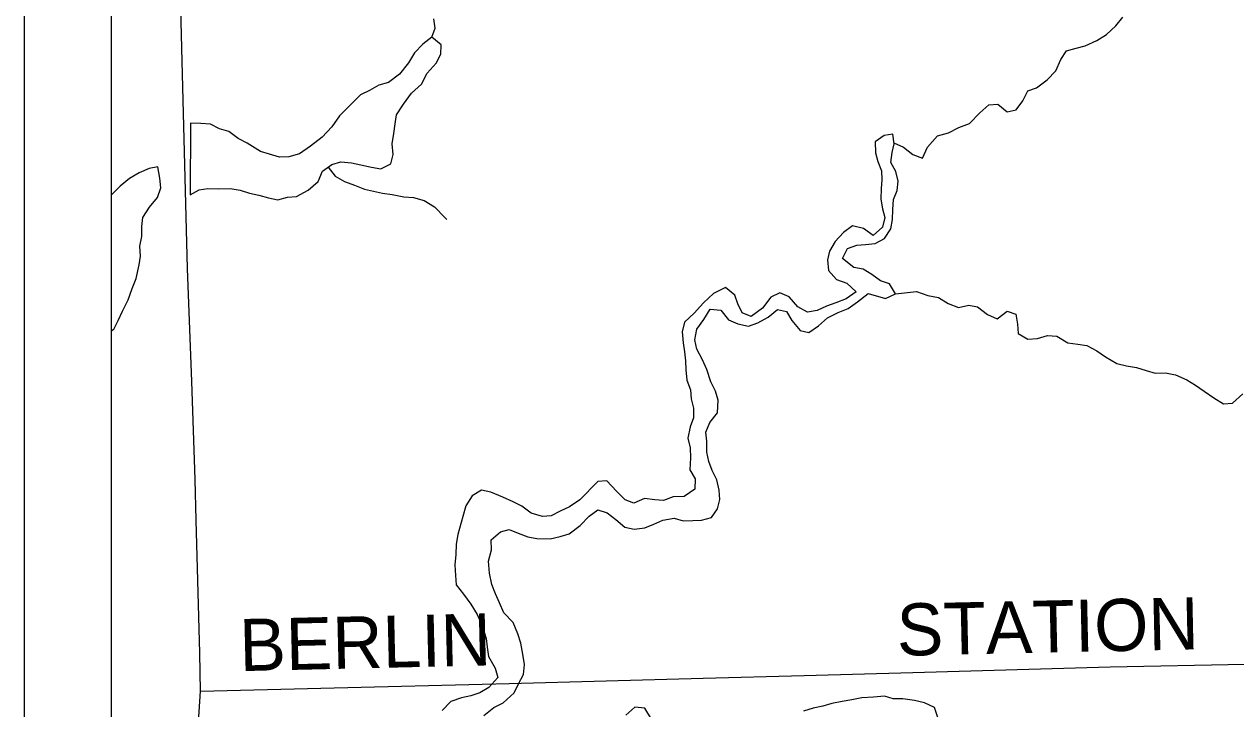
# Model space of a CAD drawing. Extents: x 0 to 34, y 0 to 22.
# Drawn here: x 2.895 to 4.215, y 16.527 to 17.274 of the extents above; entities that cross this region are included whole.
import ezdxf

# ---------------------------------------------------------------- set-up
doc = ezdxf.new("R2010")
doc.units = 0
for name, color, linetype in [('GM_X_Corporation', 7, 'Continuous'), ('GM_X_County_Road', 7, 'Continuous'), ('GM_X_County_Road_Text', 7, 'Continuous'), ('GM_X_Major_Lake', 7, 'Continuous'), ('GM_X_Minor_River', 7, 'Continuous'), ('SH_Data', 7, 'Continuous')]:
    doc.layers.add(name, color=color, linetype=linetype)

msp = doc.modelspace()

# ---------------------------------------------------------------- linework, layer by layer
at = {"layer": 'GM_X_Corporation'}
msp.add_lwpolyline([(2.9895, 20.1176), (2.9895, 14.989), (3.1061, 14.9902), (3.7218, 15.0051), (5.1362, 15.0301), (5.7825, 15.0418), (6.0746, 15.0468), (7.3134, 15.0684), (7.3375, 15.0689), (7.3129, 15.9614), (7.3097, 16.0633), (7.3049, 16.5704), (7.3046, 16.5913), (7.2998, 16.7507), (7.2943, 16.935), (7.2911, 17.0516), (7.2872, 17.1772), (7.283, 17.3071)], dxfattribs=at)
at = {"layer": 'GM_X_County_Road'}
for points in [[(3.1089, 15.8232), (3.1084, 15.9273), (3.111, 16.0453), (3.109, 16.1457), (3.1029, 16.1604), (3.0973, 16.1762), (3.088, 16.1981), (3.0786, 16.2241), (3.076, 16.2381), (3.0753, 16.2506), (3.0747, 16.2617), (3.0751, 16.278), (3.0739, 16.3103), (3.0741, 16.3491), (3.0868, 16.5462), (3.0859, 16.5875), (3.0837, 16.6669), (3.0819, 16.7328), (3.081, 16.7772), (3.0772, 16.8841), (3.0725, 17.0072), (3.0711, 17.0638), (3.0667, 17.2336), (3.0632, 17.3772)], [(3.0868, 16.5462), (3.2178, 16.5495), (3.4231, 16.5547), (3.6348, 16.5603), (3.7448, 16.5633), (3.8634, 16.5665), (4.0786, 16.5729), (4.3729, 16.5785), (4.4746, 16.5806), (4.5316, 16.5818), (4.6181, 16.584), (4.7425, 16.5872), (4.8652, 16.5899), (4.991, 16.5929), (5.1099, 16.5961), (5.1663, 16.5967), (5.184, 16.597), (5.1987, 16.5975), (5.2134, 16.598), (5.2312, 16.5988), (5.2512, 16.5993), (5.2808, 16.6002)]]:
    msp.add_lwpolyline(points, dxfattribs=at)
at = {"layer": 'GM_X_Major_Lake'}
for points in [[(3.0755, 17.0876), (3.0853, 17.093), (3.0948, 17.0946), (3.1066, 17.0943), (3.1192, 17.0944), (3.1298, 17.0926), (3.1401, 17.0893), (3.1504, 17.0871), (3.1607, 17.0845), (3.171, 17.0823), (3.1816, 17.085), (3.1915, 17.0859), (3.204, 17.0928), (3.2149, 17.102), (3.2198, 17.1135), (3.23, 17.1208), (3.2399, 17.1235), (3.2513, 17.1225), (3.2616, 17.1203), (3.273, 17.1177), (3.2833, 17.1159), (3.2943, 17.1213), (3.2968, 17.1316), (3.2956, 17.1434), (3.2974, 17.1544), (3.2988, 17.165), (3.3006, 17.1749), (3.3081, 17.1864), (3.3168, 17.1986), (3.3277, 17.2082), (3.3337, 17.2204), (3.3435, 17.2312), (3.3487, 17.2411), (3.349, 17.2514), (3.3391, 17.2596), (3.3292, 17.252), (3.3202, 17.2424), (3.3134, 17.2317), (3.3037, 17.2194), (3.2916, 17.2102), (3.281, 17.2071), (3.2711, 17.2013), (3.2613, 17.1967), (3.2503, 17.1859), (3.2383, 17.1737), (3.23, 17.1618), (3.2195, 17.1507), (3.2066, 17.1407), (3.1945, 17.1323), (3.1831, 17.1292), (3.1729, 17.1287), (3.1618, 17.132), (3.1523, 17.135), (3.1377, 17.144), (3.1278, 17.1492), (3.1175, 17.1568), (3.1076, 17.1597), (3.0976, 17.1646), (3.087, 17.1656), (3.0759, 17.1659)], [(3.0759, 17.1659), (3.0755, 17.0876)], [(3.4789, 16.7149), (3.4888, 16.718), (3.5008, 16.7269), (3.5103, 16.7372), (3.5201, 16.7441), (3.53, 16.7408), (3.5396, 16.7333), (3.5492, 16.725), (3.5595, 16.7228), (3.5712, 16.7244), (3.5811, 16.7283), (3.5909, 16.7329), (3.6031, 16.7349), (3.613, 16.732), (3.6236, 16.7324), (3.6331, 16.7329), (3.6438, 16.7356), (3.6505, 16.7452), (3.6531, 16.7551), (3.6523, 16.7653), (3.6495, 16.7767), (3.6445, 16.7869), (3.641, 16.7968), (3.6386, 16.807), (3.6389, 16.8188), (3.6376, 16.8287), (3.6421, 16.8394), (3.6504, 16.8497), (3.651, 16.8638), (3.6483, 16.8736), (3.6432, 16.8835), (3.6389, 16.8971), (3.6339, 16.9077), (3.6277, 16.9191), (3.6257, 16.9293), (3.6279, 16.9411), (3.6354, 16.9518), (3.6425, 16.9629), (3.6539, 16.9619), (3.6624, 16.9513), (3.6727, 16.9468), (3.6841, 16.9442), (3.6944, 16.9481), (3.7057, 16.9543), (3.7159, 16.9624), (3.7258, 16.9605), (3.7316, 16.9507), (3.7405, 16.9398), (3.75, 16.9376), (3.7606, 16.9449), (3.7704, 16.9533), (3.7818, 16.9591), (3.7928, 16.9637), (3.803, 16.971), (3.8147, 16.9799), (3.8337, 16.9747), (3.8443, 16.9797), (3.8378, 16.9907), (3.8282, 16.9937), (3.8187, 17.0008), (3.8091, 17.0064), (3.7992, 17.0083), (3.7866, 17.018), (3.7922, 17.0291), (3.8024, 17.0326), (3.8119, 17.0335), (3.8222, 17.0347), (3.8324, 17.0401), (3.8395, 17.0504), (3.8413, 17.0607), (3.8416, 17.0717), (3.8423, 17.0824), (3.8464, 17.0923), (3.8474, 17.1025), (3.8447, 17.1132), (3.8393, 17.123), (3.8407, 17.1337), (3.8429, 17.1432), (3.8417, 17.1538), (3.8322, 17.1522), (3.8223, 17.1453), (3.8228, 17.1335), (3.8252, 17.124), (3.8291, 17.1138), (3.8295, 17.1039), (3.8289, 17.0944), (3.8286, 17.083), (3.8302, 17.0724), (3.833, 17.0629), (3.8304, 17.0522), (3.8202, 17.0434), (3.8095, 17.0509), (3.7977, 17.0539), (3.7878, 17.0466), (3.7788, 17.0366), (3.7724, 17.0263), (3.7702, 17.0168), (3.7715, 17.005), (3.7803, 16.9952), (3.7914, 16.9911), (3.8017, 16.9817)], [(2.9895, 16.9392), (2.9924, 16.941), (2.9968, 16.9505), (3.0017, 16.9608), (3.008, 16.973), (3.0121, 16.9856), (3.0166, 16.9963), (3.0199, 17.0112), (3.0213, 17.0207), (3.0205, 17.0317), (3.0226, 17.042), (3.0229, 17.053), (3.024, 17.0629), (3.0311, 17.074), (3.0398, 17.0847), (3.0435, 17.0953), (3.0424, 17.1057), (3.0402, 17.1181), (3.0307, 17.1165), (3.0197, 17.1115), (3.0092, 17.1053), (2.999, 17.0969), (2.9895, 17.0873)], [(3.8017, 16.9817), (3.7908, 16.974), (3.7794, 16.9697), (3.7691, 16.9662), (3.7589, 16.9616), (3.7487, 16.9596), (3.738, 16.9656), (3.7284, 16.9762), (3.7184, 16.9806), (3.7086, 16.976), (3.6996, 16.9641), (3.6871, 16.9549), (3.6772, 16.959), (3.6725, 16.9689), (3.6694, 16.9783), (3.6591, 16.9866), (3.6462, 16.9801), (3.6352, 16.9697), (3.6251, 16.9586), (3.6145, 16.9486), (3.6119, 16.9383), (3.6128, 16.9262), (3.6144, 16.9163), (3.6156, 16.9064), (3.6157, 16.8969), (3.617, 16.8856), (3.6209, 16.8749), (3.6217, 16.8651), (3.6241, 16.8548), (3.6242, 16.8442), (3.6205, 16.8346), (3.6179, 16.8221), (3.6207, 16.8115), (3.6208, 16.8008), (3.6201, 16.7875), (3.6259, 16.7777), (3.6256, 16.7666), (3.6139, 16.7586), (3.6021, 16.7581), (3.5915, 16.7542), (3.582, 16.7549), (3.5709, 16.7563), (3.5592, 16.7513), (3.5497, 16.755), (3.5401, 16.7644), (3.5297, 16.7758), (3.5198, 16.7749), (3.5002, 16.755), (3.4889, 16.7473), (3.479, 16.7427), (3.4692, 16.7373), (3.4597, 16.7368), (3.4471, 16.7405), (3.4371, 16.748), (3.4276, 16.7529), (3.4165, 16.7578), (3.4032, 16.7633), (3.3932, 16.7655), (3.383, 16.7594), (3.3759, 16.7483), (3.3726, 16.7369), (3.3674, 16.7171), (3.3656, 16.7064), (3.365, 16.6954), (3.3639, 16.684), (3.3648, 16.6722), (3.3656, 16.6623), (3.3733, 16.6521), (3.3814, 16.6412), (3.3884, 16.6298), (3.3934, 16.6184), (3.3981, 16.6037), (3.3993, 16.5942), (3.4009, 16.5839), (3.4079, 16.5714), (3.411, 16.5612), (3.4012, 16.5501), (3.3914, 16.5443), (3.3815, 16.5412), (3.3713, 16.5388), (3.3595, 16.5349), (3.3501, 16.525)], [(3.3958, 16.5196), (3.4064, 16.5285), (3.4166, 16.5335), (3.4287, 16.5442), (3.4335, 16.5542), (3.4388, 16.5645), (3.4398, 16.5751), (3.4382, 16.5865), (3.4358, 16.5986), (3.4327, 16.6089), (3.4276, 16.621), (3.4176, 16.6316), (3.4126, 16.6425), (3.4083, 16.6524), (3.4044, 16.6626), (3.4017, 16.6748), (3.4008, 16.6881), (3.4041, 16.7003), (3.4036, 16.7113), (3.4138, 16.7201), (3.4233, 16.7225), (3.4332, 16.7184), (3.4435, 16.7146), (3.4534, 16.7128), (3.4679, 16.7122), (3.4789, 16.7149)], [(3.8906, 16.5175), (3.8871, 16.5285), (3.876, 16.5334), (3.865, 16.5359), (3.8524, 16.5377), (3.8421, 16.538), (3.8326, 16.5406), (3.8205, 16.5398), (3.8079, 16.5389), (3.7969, 16.5369), (3.7863, 16.5349), (3.7749, 16.5326), (3.7654, 16.5298), (3.7548, 16.5275), (3.7441, 16.5243)], [(3.5784, 16.5158), (3.5711, 16.5275), (3.5604, 16.5286), (3.5506, 16.5201)]]:
    msp.add_lwpolyline(points, dxfattribs=at)
at = {"layer": 'GM_X_Minor_River'}
for points in [[(3.3391, 17.2596), (3.3424, 17.2695), (3.3412, 17.2798)], [(3.8428, 17.1442), (3.8532, 17.1398), (3.8632, 17.1316), (3.8738, 17.1275), (3.8794, 17.1397), (3.8904, 17.1519), (3.9021, 17.1554), (3.9135, 17.1612), (3.9252, 17.1655), (3.9365, 17.177), (3.9463, 17.1858), (3.9559, 17.1867), (3.9662, 17.178), (3.9761, 17.1804), (3.9832, 17.1903), (3.9888, 17.201), (3.9983, 17.2045), (4.01, 17.2129), (4.0194, 17.2229), (4.0246, 17.2351), (4.031, 17.2447), (4.0416, 17.2478), (4.0511, 17.2501), (4.064, 17.2559), (4.0746, 17.2625), (4.0848, 17.2721), (4.0923, 17.2816)], [(3.2258, 17.1178), (3.2335, 17.1079), (3.2438, 17.1023), (3.2545, 17.0982), (3.2656, 17.0937), (3.2755, 17.0915), (3.285, 17.0893), (3.2957, 17.0879), (3.3083, 17.0853), (3.3189, 17.0846), (3.3307, 17.0813), (3.3418, 17.0745), (3.3534, 17.0625), (3.3553, 17.0606)], [(3.8443, 16.9797), (3.8675, 16.9822), (3.8797, 16.9777), (3.8915, 16.9756), (3.9019, 16.9692), (3.9133, 16.9647), (3.9243, 16.9671), (3.9338, 16.9653), (3.9446, 16.957), (3.9553, 16.9525), (3.9662, 16.9606), (3.9757, 16.9576), (3.9774, 16.9466), (3.9782, 16.9363), (3.9889, 16.93), (3.9992, 16.9308), (4.0102, 16.9343), (4.0205, 16.9336), (4.0323, 16.9261), (4.0434, 16.9247), (4.0529, 16.9233), (4.064, 16.9176), (4.0735, 16.9109), (4.0858, 16.9038), (4.0964, 16.9012), (4.1071, 16.8994), (4.1178, 16.896), (4.1277, 16.8931), (4.1387, 16.8935), (4.1498, 16.8913), (4.162, 16.8857), (4.1715, 16.8801), (4.1811, 16.8733), (4.1914, 16.8662), (4.2021, 16.8598), (4.212, 16.8603), (4.223, 16.8706)]]:
    msp.add_lwpolyline(points, dxfattribs=at)
at = {"layer": 'SH_Data'}
msp.add_line((2.8945, 20.8873), (2.8945, 13.8873), dxfattribs=at)

# ---------------------------------------------------------------- texts
at = {"layer": 'GM_X_County_Road_Text'}
for s, rotation, p in [('STATION', 1.2521, (3.8464, 16.5847)), ('BERLIN', 1.3322, (3.1297, 16.568))]:
    msp.add_text(s, height=0.05682, rotation=rotation, dxfattribs=at).set_placement(p)

doc.saveas('drawing.dxf')
